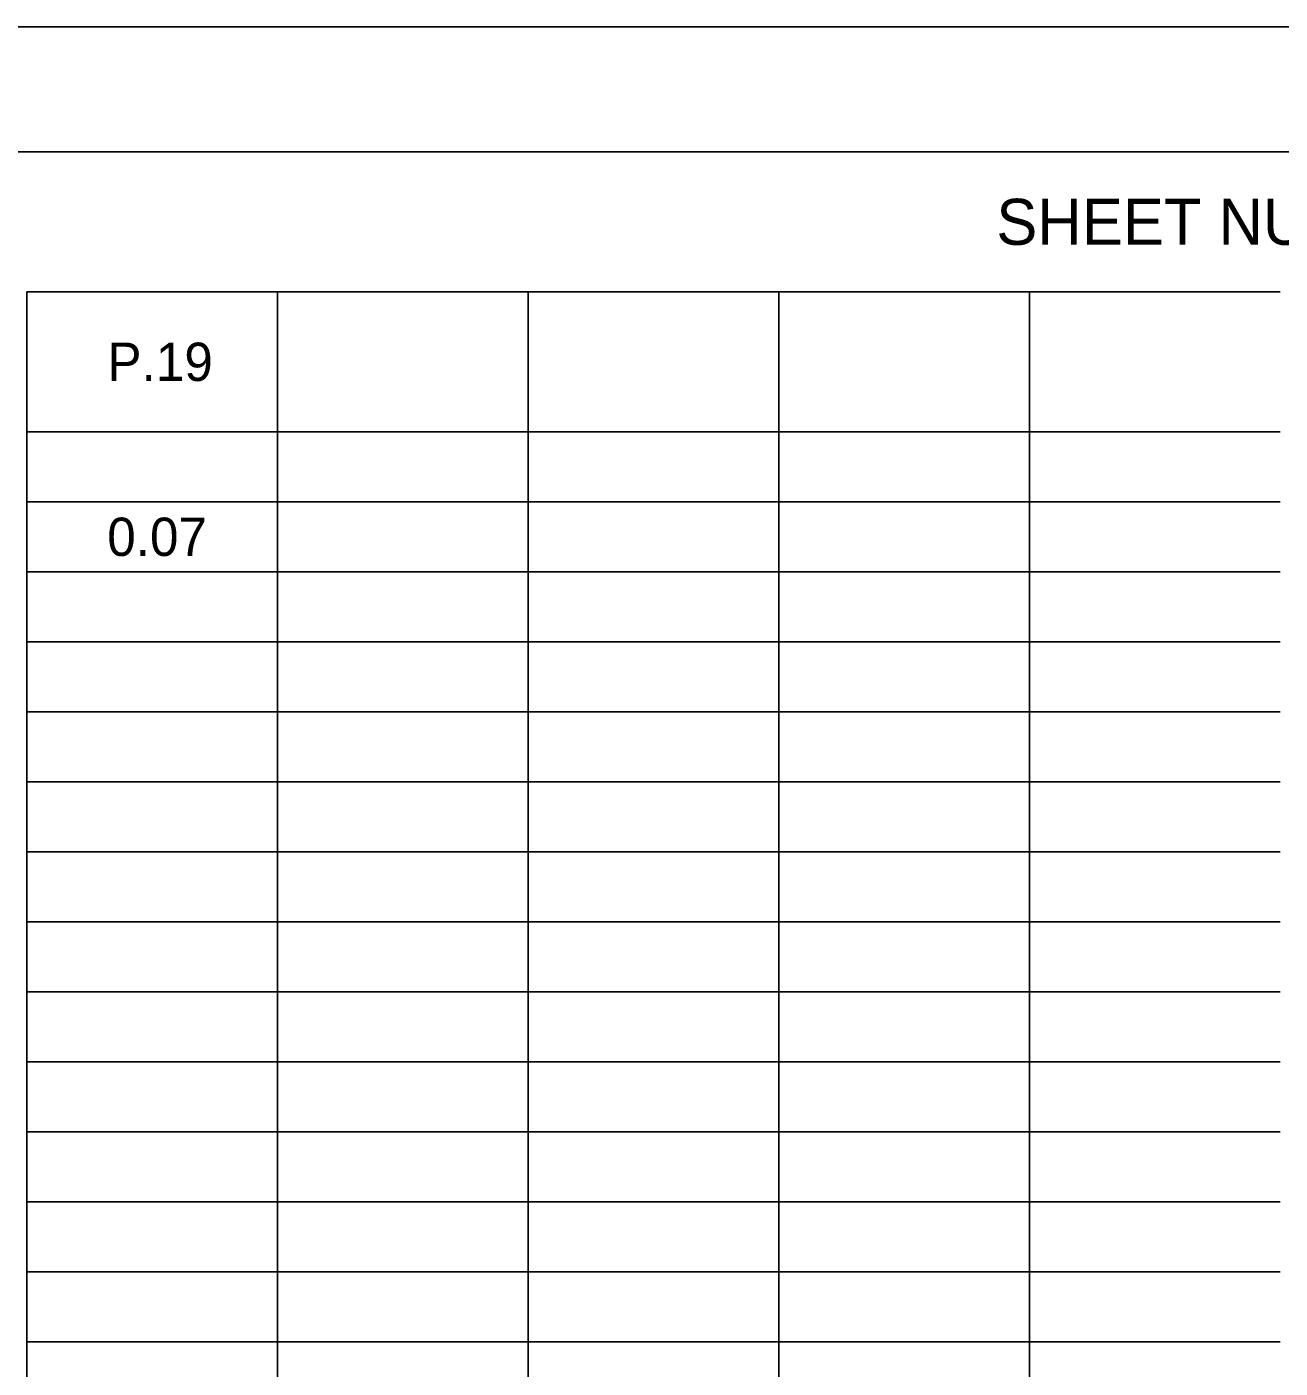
# Model space of a CAD drawing. Extents: x 0 to 34, y 0 to 22.
# Drawn here: x 3.51 to 8.52, y 16.63 to 22 of the extents above; entities that cross this region are included whole.
import ezdxf

# ---------------------------------------------------------------- set-up
doc = ezdxf.new("R2010")
doc.units = 0
for name, color, linetype in [('SH_Border', 7, 'Continuous'), ('SH_Cut_Line', 7, 'Continuous'), ('SH_Text', 7, 'Continuous')]:
    doc.layers.add(name, color=color, linetype=linetype)

msp = doc.modelspace()

# ---------------------------------------------------------------- linework, layer by layer
at = {"layer": 'SH_Border'}
msp.add_lwpolyline([(1.5, 21.5), (33.5, 21.5), (33.5, 0.5), (1.5, 0.5)], close=True, dxfattribs=at)
at = {"layer": 'SH_Cut_Line'}
msp.add_lwpolyline([(0, 0), (34, 0), (34, 22), (0, 22)], close=True, dxfattribs=at)
at = {"layer": 'SH_Text'}
for p, q in [((3.5051, 21.5), (4.5076, 21.5)), ((4.5076, 21.5), (5.5101, 21.5)), ((5.5101, 21.5), (6.5126, 21.5)), ((6.5126, 21.5), (7.5152, 21.5)), ((7.5152, 21.5), (8.5177, 21.5)), ((3.5051, 20.94), (4.5076, 20.94)), ((3.5051, 20.94), (3.5051, 20.66)), ((4.5076, 20.94), (5.5101, 20.94)), ((4.5076, 20.94), (4.5076, 20.66)), ((5.5101, 20.94), (6.5126, 20.94)), ((5.5101, 20.94), (5.5101, 20.66)), ((6.5126, 20.94), (7.5152, 20.94)), ((6.5126, 20.94), (6.5126, 20.66)), ((7.5152, 20.94), (8.5177, 20.94)), ((7.5152, 20.94), (7.5152, 20.66)), ((3.5051, 20.66), (3.5051, 20.38)), ((4.5076, 20.66), (4.5076, 20.38)), ((5.5101, 20.66), (5.5101, 20.38)), ((6.5126, 20.66), (6.5126, 20.38)), ((7.5152, 20.66), (7.5152, 20.38)), ((3.5051, 20.38), (4.5076, 20.38)), ((3.5051, 20.38), (3.5051, 20.1)), ((4.5076, 20.38), (5.5101, 20.38)), ((4.5076, 20.38), (4.5076, 20.1)), ((5.5101, 20.38), (6.5126, 20.38)), ((5.5101, 20.38), (5.5101, 20.1)), ((6.5126, 20.38), (7.5152, 20.38)), ((6.5126, 20.38), (6.5126, 20.1)), ((7.5152, 20.38), (8.5177, 20.38)), ((7.5152, 20.38), (7.5152, 20.1)), ((3.5051, 20.1), (4.5076, 20.1)), ((3.5051, 20.1), (3.5051, 18.7)), ((4.5076, 20.1), (5.5101, 20.1)), ((4.5076, 20.1), (4.5076, 18.7)), ((5.5101, 20.1), (6.5126, 20.1)), ((5.5101, 20.1), (5.5101, 18.7)), ((6.5126, 20.1), (7.5152, 20.1)), ((6.5126, 20.1), (6.5126, 18.7)), ((7.5152, 20.1), (8.5177, 20.1)), ((7.5152, 20.1), (7.5152, 18.7)), ((3.5051, 19.82), (4.5076, 19.82)), ((4.5076, 19.82), (5.5101, 19.82)), ((5.5101, 19.82), (6.5126, 19.82)), ((6.5126, 19.82), (7.5152, 19.82)), ((7.5152, 19.82), (8.5177, 19.82)), ((3.5051, 19.54), (4.5076, 19.54)), ((4.5076, 19.54), (5.5101, 19.54)), ((5.5101, 19.54), (6.5126, 19.54)), ((6.5126, 19.54), (7.5152, 19.54)), ((7.5152, 19.54), (8.5177, 19.54)), ((3.5051, 19.26), (4.5076, 19.26)), ((4.5076, 19.26), (5.5101, 19.26)), ((5.5101, 19.26), (6.5126, 19.26)), ((6.5126, 19.26), (7.5152, 19.26)), ((7.5152, 19.26), (8.5177, 19.26)), ((3.5051, 18.98), (4.5076, 18.98)), ((4.5076, 18.98), (5.5101, 18.98)), ((5.5101, 18.98), (6.5126, 18.98)), ((6.5126, 18.98), (7.5152, 18.98)), ((7.5152, 18.98), (8.5177, 18.98)), ((3.5051, 18.7), (4.5076, 18.7)), ((3.5051, 18.7), (3.5051, 18.14)), ((4.5076, 18.7), (5.5101, 18.7)), ((4.5076, 18.7), (4.5076, 18.14)), ((5.5101, 18.7), (6.5126, 18.7)), ((5.5101, 18.7), (5.5101, 18.14)), ((6.5126, 18.7), (7.5152, 18.7)), ((6.5126, 18.7), (6.5126, 18.14)), ((7.5152, 18.7), (8.5177, 18.7)), ((7.5152, 18.7), (7.5152, 18.14)), ((3.5051, 18.42), (4.5076, 18.42)), ((4.5076, 18.42), (5.5101, 18.42)), ((5.5101, 18.42), (6.5126, 18.42)), ((6.5126, 18.42), (7.5152, 18.42)), ((7.5152, 18.42), (8.5177, 18.42)), ((3.5051, 18.14), (4.5076, 18.14)), ((3.5051, 18.14), (3.5051, 17.86)), ((4.5076, 18.14), (5.5101, 18.14)), ((4.5076, 18.14), (4.5076, 17.86)), ((5.5101, 18.14), (6.5126, 18.14)), ((5.5101, 18.14), (5.5101, 17.86)), ((6.5126, 18.14), (7.5152, 18.14)), ((6.5126, 18.14), (6.5126, 17.86)), ((7.5152, 18.14), (8.5177, 18.14)), ((7.5152, 18.14), (7.5152, 17.86)), ((3.5051, 17.86), (4.5076, 17.86)), ((3.5051, 17.86), (3.5051, 17.58)), ((4.5076, 17.86), (5.5101, 17.86)), ((4.5076, 17.86), (4.5076, 17.58)), ((5.5101, 17.86), (6.5126, 17.86)), ((5.5101, 17.86), (5.5101, 17.58)), ((6.5126, 17.86), (7.5152, 17.86)), ((6.5126, 17.86), (6.5126, 17.58)), ((7.5152, 17.86), (8.5177, 17.86)), ((7.5152, 17.86), (7.5152, 17.58)), ((3.5051, 17.58), (4.5076, 17.58)), ((3.5051, 17.58), (3.5051, 17.3)), ((4.5076, 17.58), (5.5101, 17.58)), ((4.5076, 17.58), (4.5076, 17.3)), ((5.5101, 17.58), (6.5126, 17.58)), ((5.5101, 17.58), (5.5101, 17.3)), ((6.5126, 17.58), (7.5152, 17.58)), ((6.5126, 17.58), (6.5126, 17.3)), ((7.5152, 17.58), (8.5177, 17.58)), ((7.5152, 17.58), (7.5152, 17.3)), ((3.5051, 17.3), (4.5076, 17.3)), ((3.5051, 17.3), (3.5051, 17.02)), ((4.5076, 17.3), (5.5101, 17.3)), ((4.5076, 17.3), (4.5076, 17.02)), ((5.5101, 17.3), (6.5126, 17.3)), ((5.5101, 17.3), (5.5101, 17.02)), ((6.5126, 17.3), (7.5152, 17.3)), ((6.5126, 17.3), (6.5126, 17.02)), ((7.5152, 17.3), (8.5177, 17.3)), ((7.5152, 17.3), (7.5152, 17.02)), ((3.5051, 17.02), (4.5076, 17.02)), ((3.5051, 17.02), (3.5051, 16.74)), ((4.5076, 17.02), (5.5101, 17.02)), ((4.5076, 17.02), (4.5076, 16.74)), ((5.5101, 17.02), (6.5126, 17.02)), ((5.5101, 17.02), (5.5101, 16.74)), ((6.5126, 17.02), (7.5152, 17.02)), ((6.5126, 17.02), (6.5126, 16.74)), ((7.5152, 17.02), (8.5177, 17.02)), ((7.5152, 17.02), (7.5152, 16.74)), ((3.5051, 16.74), (4.5076, 16.74)), ((3.5051, 16.74), (3.5051, 16.18)), ((4.5076, 16.74), (5.5101, 16.74)), ((4.5076, 16.74), (4.5076, 16.18)), ((5.5101, 16.74), (6.5126, 16.74)), ((5.5101, 16.74), (5.5101, 16.18)), ((6.5126, 16.74), (7.5152, 16.74)), ((6.5126, 16.74), (6.5126, 16.18)), ((7.5152, 16.74), (8.5177, 16.74)), ((7.5152, 16.74), (7.5152, 16.18))]:
    msp.add_line(p, q, dxfattribs=at)

# ---------------------------------------------------------------- texts
for s, height, p in [('SHEET NUM.', 0.184, (7.3825, 21.128)), ('P.19', 0.15333, (3.8273, 20.5833)), ('0.07', 0.15333, (3.8266, 19.8833))]:
    msp.add_text(s, height=height, dxfattribs=at).set_placement(p)

doc.saveas('drawing.dxf')
